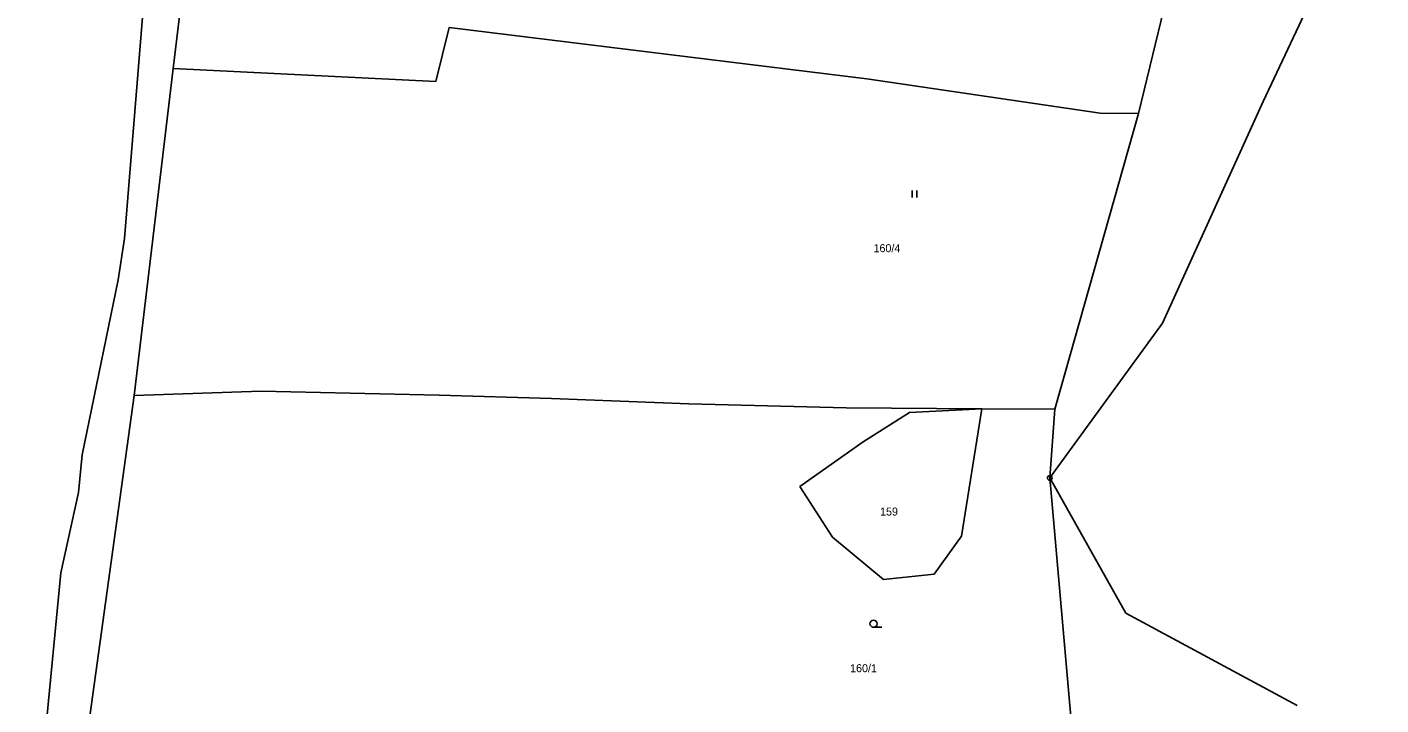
# Model space of a CAD drawing. Extents: x -717366 to -716792, y -1145485 to -1142762.
# Drawn here: x -717336.1 to -717192.3, y -1144197.3 to -1144125.3 of the extents above; entities that cross this region are included whole.
import ezdxf

# ---------------------------------------------------------------- set-up
doc = ezdxf.new("R2010")
doc.units = 0
doc.layers.add('Vrstva 1', color=7, linetype='Continuous')

msp = doc.modelspace()

# ---------------------------------------------------------------- linework, layer by layer
at = {"layer": 'Vrstva 1'}
for p, q in [((-717325.78, -1144147.72), (-717321.01, -1144089.08)), ((-717218.08, -1144134.44), (-717209.99, -1144101.07)), ((-717192.34, -1144106.5), (-717204.83, -1144133.17)), ((-717319.63, -1144121.46), (-717320.6, -1144129.66)), ((-717291.31, -1144125.32), (-717292.71, -1144131.05)), ((-717246.93, -1144130.78), (-717291.31, -1144125.32)), ((-717324.73, -1144164.4), (-717320.6, -1144129.66)), ((-717320.6, -1144129.66), (-717292.71, -1144131.05)), ((-717222.16, -1144134.41), (-717246.93, -1144130.78)), ((-717204.83, -1144133.17), (-717215.54, -1144156.73)), ((-717226.96, -1144165.84), (-717218.08, -1144134.44)), ((-717218.08, -1144134.44), (-717222.16, -1144134.41)), ((-717242.124, -1144143.377), (-717242.124, -1144142.627)), ((-717241.624, -1144142.627), (-717241.624, -1144143.377)), ((-717326.43, -1144152.12), (-717325.78, -1144147.72)), ((-717330.28, -1144170.71), (-717326.43, -1144152.12)), ((-717215.54, -1144156.73), (-717227.51, -1144173.16)), ((-717324.73, -1144164.4), (-717331.38, -1144212.21)), ((-717324.73, -1144164.4), (-717311.25, -1144163.94)), ((-717311.25, -1144163.94), (-717292.37, -1144164.35)), ((-717292.37, -1144164.35), (-717280.44, -1144164.72)), ((-717280.44, -1144164.72), (-717265.83, -1144165.3)), ((-717265.83, -1144165.3), (-717249.14, -1144165.71)), ((-717249.14, -1144165.71), (-717234.74, -1144165.8)), ((-717247.34, -1144169.31), (-717242.41, -1144166.19)), ((-717234.74, -1144165.8), (-717242.41, -1144166.19)), ((-717236.9, -1144179.33), (-717234.74, -1144165.8)), ((-717226.96, -1144165.84), (-717234.74, -1144165.8)), ((-717226.96, -1144165.84), (-717227.51, -1144173.16)), ((-717254.04, -1144174.08), (-717247.34, -1144169.31)), ((-717330.65, -1144174.69), (-717330.28, -1144170.71)), ((-717227.51, -1144173.16), (-717225.15, -1144199.74)), ((-717227.51, -1144173.16), (-717219.42, -1144187.51)), ((-717332.55, -1144183.22), (-717330.65, -1144174.69)), ((-717254.04, -1144174.08), (-717250.6, -1144179.46)), ((-717250.6, -1144179.46), (-717245.18, -1144183.93)), ((-717239.77, -1144183.39), (-717236.9, -1144179.33)), ((-717336.12, -1144220.35), (-717332.55, -1144183.22)), ((-717245.18, -1144183.93), (-717239.77, -1144183.39)), ((-717219.42, -1144187.51), (-717201.23, -1144197.31)), ((-717246.225, -1144189.017), (-717245.35, -1144189.017))]:
    msp.add_line(p, q, dxfattribs=at)
for centre, radius in [((-717227.51, -1144173.16), 0.25), ((-717227.51, -1144173.16), 0.005), ((-717246.226, -1144188.643), 0.375)]:
    msp.add_circle(centre, radius, dxfattribs=at)

# ---------------------------------------------------------------- texts
for s, p in [('160/4', (-717246.225, -1144149.179)), ('159', (-717245.53, -1144177.15)), ('160/1', (-717248.712, -1144193.783))]:
    msp.add_text(s, height=0.85, dxfattribs=at).set_placement(p)

doc.saveas('drawing.dxf')
